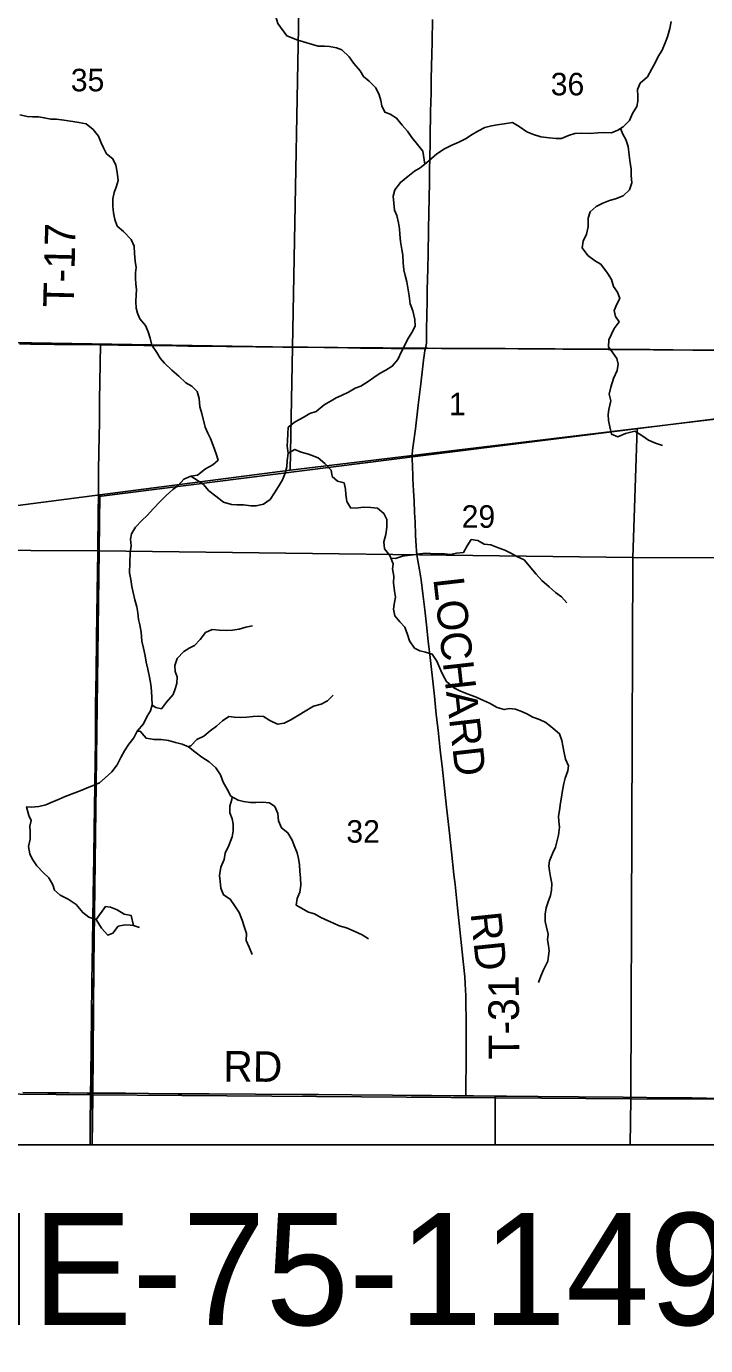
# Model space of a CAD drawing. Extents: x 0 to 1391, y -24 to 440.
# Drawn here: x 561.39 to 586.61, y 365.71 to 414.73 of the extents above; entities that cross this region are included whole.
import ezdxf

# ---------------------------------------------------------------- set-up
doc = ezdxf.new("R2010")
doc.units = 0
for name, color, linetype in [('GM_X_County_Road', 7, 'Continuous'), ('GM_X_County_Road_Text', 7, 'Continuous'), ('GM_X_Minor_Lake', 7, 'Continuous'), ('GM_X_Minor_River', 7, 'Continuous'), ('GM_X_Section', 7, 'Continuous'), ('GM_X_Section_Text', 7, 'Continuous'), ('GM_X_Township', 7, 'Continuous'), ('GM_X_Township_Road', 7, 'Continuous'), ('GM_X_Township_Road_Text', 7, 'Continuous'), ('SH_Text', 7, 'Continuous')]:
    doc.layers.add(name, color=color, linetype=linetype)

msp = doc.modelspace()

# ---------------------------------------------------------------- linework, layer by layer
at = {"layer": 'GM_X_County_Road'}
for points in [[(564.059, 397.238), (564.062, 397.431), (564.068, 398.202), (564.075, 398.935), (564.087, 399.469), (564.096, 400.053), (564.106, 400.997), (564.113, 401.358), (564.127, 402.339), (564.134, 402.762), (564.135, 402.895)], [(563.769, 375.097), (563.778, 375.648), (563.793, 376.916), (563.801, 377.91), (563.818, 379.215), (563.845, 380.668), (563.868, 382.408), (563.892, 383.874), (563.897, 384.905), (563.912, 385.712), (563.925, 386.508), (563.936, 387.464), (563.947, 388.148), (563.958, 389.515), (563.973, 390.695), (563.992, 391.975), (564.012, 393.715), (564.034, 395.207), (564.051, 396.735), (564.059, 397.238)], [(561.256, 375.121), (562.187, 375.111), (562.97, 375.104), (563.641, 375.098), (563.769, 375.097)], [(563.758, 373.178), (563.758, 373.598), (563.758, 374.045), (563.766, 374.89), (563.769, 375.097)], [(563.769, 375.097), (565.065, 375.091), (565.922, 375.085), (567.028, 375.073), (568.171, 375.067), (569.899, 375.056), (571.638, 375.043), (572.235, 375.04), (573.478, 375.033), (574.981, 375.015), (575.677, 375.009), (576.435, 375), (577.243, 374.994), (577.711, 374.991)], [(577.711, 374.991), (577.988, 374.99), (578.802, 374.985)], [(578.802, 374.985), (579.218, 374.982), (580.399, 374.97), (581.89, 374.958), (583.555, 374.941), (585.295, 374.925), (586.102, 374.916), (586.649, 374.909), (588.364, 374.891), (588.829, 374.885)]]:
    msp.add_lwpolyline(points, dxfattribs=at)
at = {"layer": 'GM_X_Minor_Lake'}
for points in [[(565.369, 381.317), (565.278, 381.693), (565.013, 381.737), (564.757, 381.901), (564.508, 381.997), (564.318, 382.024), (563.972, 381.544)], [(563.972, 381.544), (564.175, 381.224), (564.406, 380.962), (564.597, 381.041), (564.799, 381.302), (565.059, 381.349), (565.249, 381.338), (565.369, 381.317)]]:
    msp.add_lwpolyline(points, dxfattribs=at)
at = {"layer": 'GM_X_Minor_River'}
for points in [[(570.75, 418), (570.656, 415.079), (570.729, 414.828), (571.057, 414.376), (571.464, 414.211), (572.228, 413.996)], [(571.912, 400.349), (572.142, 400.413), (572.445, 400.665), (572.7, 400.812), (572.893, 400.922), (573.086, 401.016), (573.348, 401.14), (573.595, 401.287), (573.811, 401.366), (574.074, 401.535), (574.29, 401.683), (574.523, 401.845), (574.731, 401.955), (574.971, 402.102), (575.182, 402.348), (575.318, 402.65), (575.43, 402.86), (575.542, 403.094), (575.7, 403.349), (575.827, 403.59), (575.81, 403.841), (575.741, 404.162), (575.639, 404.415), (575.608, 404.72), (575.567, 404.942), (575.513, 405.24), (575.449, 405.477), (575.408, 405.676), (575.376, 405.943), (575.367, 406.232), (575.333, 406.438), (575.286, 406.736), (575.254, 407.01), (575.243, 407.201), (575.203, 407.43), (575.14, 407.705), (575.06, 407.897), (575.028, 408.164), (575.003, 408.416), (575.069, 408.65), (575.274, 408.927), (575.553, 409.149), (575.801, 409.342), (576.01, 409.467), (576.243, 409.659), (576.437, 409.822), (576.632, 409.986), (576.918, 410.177), (577.188, 410.316), (577.45, 410.425), (577.689, 410.549), (577.936, 410.711), (578.153, 410.835), (578.415, 410.967), (578.66, 411.038), (578.867, 411.071), (579.135, 411.103), (579.441, 411.15), (579.682, 411.008), (579.967, 410.812), (580.224, 410.715), (580.489, 410.625), (580.801, 410.581), (581.06, 410.56), (581.258, 410.563), (581.52, 410.679), (581.758, 410.75), (582.01, 410.76), (582.33, 410.753), (582.613, 410.77), (582.872, 410.78), (583.123, 410.767), (583.347, 410.868), (583.548, 411.001), (583.782, 411.232), (583.902, 411.488), (584.053, 411.751), (584.095, 411.948), (584.092, 412.138), (584.082, 412.382), (584.178, 412.615), (584.451, 412.853), (584.617, 413.146), (584.745, 413.402), (584.856, 413.605), (584.999, 413.845), (585.104, 414.117), (585.193, 414.343), (585.283, 414.646), (585.335, 414.911)], [(572.228, 413.996), (572.457, 413.993), (572.647, 413.974), (572.905, 413.931), (573.102, 413.85), (573.371, 413.601), (573.549, 413.354), (573.779, 413.075), (573.904, 412.859), (574.114, 412.695), (574.367, 412.446), (574.491, 412.185), (574.555, 411.97), (574.582, 411.78), (574.698, 411.534), (574.902, 411.461), (575.136, 411.319), (575.336, 411.063), (575.544, 410.831), (575.707, 410.599), (575.915, 410.336), (576.115, 410.096), (576.19, 409.614)], [(567.495, 398.01), (567.746, 398.053), (568.037, 398.284), (568.312, 398.44), (568.512, 398.611), (568.432, 398.848), (568.322, 399.16), (568.219, 399.42), (568.123, 399.611), (568.02, 399.832), (567.905, 400.35), (567.832, 400.593), (567.798, 400.905), (567.726, 401.156), (567.531, 401.364), (567.305, 401.488), (567.05, 401.735), (566.788, 401.951), (566.518, 402.212), (566.353, 402.404), (566.227, 402.611), (566.041, 402.886), (565.984, 403.145), (565.911, 403.374), (565.808, 403.611), (565.599, 403.864), (565.518, 404.07), (565.467, 404.26), (565.455, 404.511), (565.466, 404.753), (565.469, 404.943), (565.456, 405.163), (565.444, 405.361), (565.439, 405.573), (565.457, 405.77), (565.422, 406.006), (565.403, 406.287), (565.384, 406.56), (565.281, 406.812), (564.989, 407.105), (564.756, 407.305), (564.668, 407.549), (564.626, 407.8), (564.599, 408.051), (564.595, 408.316), (564.643, 408.558), (564.714, 408.755), (564.793, 409.004), (564.76, 409.316), (564.71, 409.574), (564.599, 409.811), (564.366, 409.996), (564.255, 410.21), (564.159, 410.401), (564.064, 410.653), (563.87, 410.891), (563.607, 411.107), (563.334, 411.156), (563.115, 411.189), (562.781, 411.239), (562.501, 411.281), (562.296, 411.284), (562.047, 411.333), (561.834, 411.366), (561.607, 411.362), (561.417, 411.379), (561.137, 411.436)], [(583.452, 410.938), (583.534, 410.727), (583.652, 410.519), (583.738, 410.259), (583.776, 409.939), (583.802, 409.74), (583.849, 409.42), (583.851, 409.191), (583.876, 408.917), (583.786, 408.66), (583.552, 408.429), (583.268, 408.314), (583.045, 408.258), (582.799, 408.164), (582.545, 408.033), (582.327, 407.832), (582.245, 407.598), (582.246, 407.278), (582.194, 407.013), (582.066, 406.742), (582.03, 406.499), (582.238, 406.213), (582.523, 406.009), (582.726, 405.891), (582.963, 405.559), (583.118, 405.327), (583.188, 405.059), (583.336, 404.858), (583.422, 404.613), (583.319, 404.41), (583.214, 404.169), (583.27, 403.947), (583.404, 403.754), (583.215, 403.507), (583.111, 403.296), (583.023, 403.077), (583.002, 402.827), (583.172, 402.595), (583.32, 402.386), (583.369, 402.172), (583.325, 401.937), (583.189, 401.644), (583.098, 401.326), (583.031, 401.061), (583.095, 400.809), (583.019, 400.491), (582.999, 400.301), (583.01, 400.088), (583.05, 399.844), (583.121, 399.576), (583.355, 399.479), (583.632, 399.603), (583.985, 399.687), (584.241, 399.521), (584.496, 399.348), (584.753, 399.244), (585.01, 399.155)], [(571.103, 398.865), (571.069, 399.131), (571.086, 399.328), (571.09, 399.593), (571.108, 399.836), (571.369, 400.037), (571.659, 400.193), (571.912, 400.349)], [(565.212, 394.42), (565.234, 395.173), (565.283, 395.422), (565.256, 395.673), (565.289, 395.878), (565.436, 396.126), (565.675, 396.373), (565.882, 396.568), (566.098, 396.8), (566.359, 397.07), (566.575, 397.294), (566.828, 397.526), (567.02, 397.668), (567.235, 397.908), (567.495, 398.01), (567.766, 397.84), (567.961, 397.701), (568.163, 397.47), (568.418, 397.27), (568.704, 397.053), (569.006, 396.958), (569.196, 396.948), (569.454, 396.952), (569.727, 396.918), (569.924, 396.915), (570.19, 396.972), (570.436, 397.151), (570.606, 397.392), (570.753, 397.633), (570.893, 397.881), (571.002, 398.13), (571.059, 398.357), (571.069, 398.6), (571.103, 398.865), (571.356, 399.013), (571.597, 398.911), (571.862, 398.839)], [(571.862, 398.839), (572.219, 398.7), (572.466, 398.481), (572.704, 398.24), (572.745, 398.004), (572.939, 397.832), (573.182, 397.774), (573.238, 397.529), (573.249, 397.338), (573.289, 397.079), (573.436, 396.832), (573.711, 396.842), (573.909, 396.86), (574.176, 396.854), (574.427, 396.826), (574.667, 396.631), (574.776, 396.4), (574.77, 396.119), (574.734, 395.853), (574.659, 395.581), (574.684, 395.322), (574.884, 395.074), (575.002, 394.764)], [(574.926, 394.965), (575.095, 394.963), (575.349, 395.049), (575.54, 395.068), (575.747, 395.094), (575.999, 395.126), (576.205, 395.152), (576.396, 395.141), (576.647, 395.128), (576.914, 395.13), (577.142, 395.109), (577.357, 395.15), (577.625, 395.183), (577.76, 395.431), (577.91, 395.663), (578.153, 395.628), (578.386, 395.493), (578.63, 395.465), (578.887, 395.361), (579.152, 395.272), (579.408, 395.144), (579.604, 395.034), (579.87, 394.905)], [(575.002, 394.764), (574.982, 394.569), (575.029, 394.302), (575.015, 394.058), (575.06, 393.738), (575.1, 393.523), (575.04, 393.259), (575.02, 393.069), (575.074, 392.824), (575.251, 392.599), (575.444, 392.411), (575.544, 392.135), (575.614, 391.897), (575.804, 391.626), (576, 391.522), (576.204, 391.479), (576.461, 391.404), (576.629, 391.148), (576.78, 390.802), (576.866, 390.61), (576.99, 390.386), (577.265, 390.151), (577.483, 390.039), (577.694, 389.957), (577.89, 389.884), (578.094, 389.81), (578.357, 389.682), (578.582, 389.585), (578.867, 389.418), (579.132, 389.343), (579.323, 389.383), (579.551, 389.362), (579.807, 389.257), (580.002, 389.168), (580.197, 389.057), (580.439, 388.975), (580.679, 388.87), (580.94, 388.65), (581.186, 388.446), (581.271, 388.2), (581.311, 388.001), (581.358, 387.734), (581.413, 387.496), (581.521, 387.258), (581.5, 387.068), (581.402, 386.797), (581.344, 386.6), (581.299, 386.343), (581.262, 386.092), (581.226, 385.88), (581.189, 385.592), (581.153, 385.38), (581.155, 385.189), (581.188, 384.975), (581.15, 384.68), (581.09, 384.43), (581.032, 384.234), (580.935, 384.023), (580.813, 383.729), (580.786, 383.54), (580.819, 383.348), (580.851, 383.127), (580.898, 382.882), (580.884, 382.639), (580.849, 382.442), (580.759, 382.201), (580.692, 381.982), (580.648, 381.739), (580.649, 381.465), (580.697, 381.259), (580.759, 381.006), (580.745, 380.786), (580.778, 380.579), (580.796, 380.381), (580.776, 380.191), (580.748, 380.002), (580.595, 379.671), (580.497, 379.437), (580.408, 379.204)], [(579.87, 394.905), (580.319, 394.381), (580.533, 394.14), (580.801, 393.905), (581.039, 393.693), (581.256, 393.528), (581.456, 393.31)], [(561.372, 385.732), (561.57, 385.721), (561.844, 385.739), (562.103, 385.811), (562.31, 385.89), (562.608, 386.014), (562.83, 386.109), (563.189, 386.255), (563.441, 386.349), (563.701, 386.459), (563.908, 386.531), (564.107, 386.626), (564.314, 386.812), (564.561, 387.036), (564.762, 387.297), (564.895, 387.568), (565.035, 387.808), (565.19, 388.063), (565.376, 388.295), (565.501, 388.536), (565.733, 388.82), (565.873, 389.098), (565.997, 389.3), (566.061, 389.519), (566.042, 389.777), (566.037, 390.035), (566.002, 390.278), (565.953, 390.544), (565.896, 390.84), (565.831, 391.106), (565.796, 391.342), (565.738, 391.623), (565.673, 391.882), (565.647, 392.223), (565.605, 392.497), (565.555, 392.694), (565.52, 392.937), (565.492, 393.165), (565.419, 393.416), (565.355, 393.698), (565.297, 393.919), (565.269, 394.177), (565.212, 394.42)], [(566.056, 389.502), (566.197, 389.426), (566.402, 389.377), (566.595, 389.624), (566.834, 389.908), (566.913, 390.119), (566.969, 390.315), (566.987, 390.557), (566.906, 390.755), (566.902, 390.983), (566.981, 391.247), (567.235, 391.5), (567.435, 391.626), (567.626, 391.721), (567.835, 391.952), (568.043, 392.207), (568.281, 392.324), (568.546, 392.289), (568.805, 392.285), (569.041, 392.296), (569.285, 392.33), (569.537, 392.402), (569.781, 392.451)], [(571.211, 388.965), (572.051, 389.476), (572.334, 389.545), (572.574, 389.668), (572.784, 389.883)], [(567.392, 387.963), (567.487, 388.003), (567.71, 388.227), (567.978, 388.351), (568.209, 388.559), (568.447, 388.722), (568.67, 388.931), (568.9, 389.086), (569.098, 389.068), (569.349, 389.048), (569.577, 389.06), (569.806, 389.086), (569.996, 389.098), (570.186, 389.088), (570.428, 388.94), (570.707, 388.806), (570.959, 388.84), (571.211, 388.965)], [(565.504, 388.539), (565.607, 388.541), (565.832, 388.28), (566.128, 388.23), (566.394, 388.233), (566.66, 388.198), (566.925, 388.118), (567.176, 388.061), (567.403, 387.959), (567.644, 387.773), (567.907, 387.572), (568.179, 387.408), (568.419, 387.184), (568.598, 386.916), (568.694, 386.642), (568.843, 386.382), (568.984, 386.13), (569.256, 385.981), (569.445, 385.933), (569.711, 385.89), (569.901, 385.895), (570.152, 385.906), (570.418, 385.879), (570.614, 385.739), (570.725, 385.48), (570.752, 385.207), (570.855, 384.947), (571.096, 384.761), (571.252, 384.494), (571.326, 384.296), (571.444, 384.021), (571.487, 383.816), (571.529, 383.572), (571.542, 383.337), (571.569, 383.079), (571.581, 382.821), (571.547, 382.564), (571.437, 382.324), (571.405, 382.076)], [(569.034, 386.102), (569.02, 386), (568.941, 385.759), (568.938, 385.509), (569.034, 385.28), (569.069, 385.09), (569.066, 384.833), (569.033, 384.613), (568.907, 384.297), (568.766, 384.012), (568.725, 383.777), (568.607, 383.484), (568.558, 383.182), (568.578, 382.969), (568.605, 382.711), (568.708, 382.459), (568.957, 382.304), (569.121, 382.059), (569.285, 381.806), (569.403, 381.524), (569.469, 381.28), (569.564, 381.021), (569.546, 380.764), (569.657, 380.512), (569.775, 380.245)], [(561.386, 385.731), (561.482, 385.412), (561.563, 385.221), (561.515, 385.009), (561.527, 384.805), (561.531, 384.532), (561.467, 384.26), (561.517, 383.987), (561.598, 383.796), (561.77, 383.543), (562.025, 383.281), (562.22, 383.096), (562.369, 382.828), (562.435, 382.638), (562.638, 382.445), (562.932, 382.296), (563.234, 382.102), (563.481, 381.802), (563.707, 381.632), (563.972, 381.544)], [(571.405, 382.076), (571.869, 381.817), (572.088, 381.758), (572.321, 381.622), (572.591, 381.494), (572.787, 381.405), (572.998, 381.309), (573.27, 381.233), (573.556, 381.112), (573.856, 380.975), (574.089, 380.832)], [(565.369, 381.317), (565.581, 381.245)]]:
    msp.add_lwpolyline(points, dxfattribs=at)
at = {"layer": 'GM_X_Section'}
for points in [[(551.455, 418), (551.127, 403.143), (571.263, 402.812), (571.559, 418)], [(571.559, 418), (571.263, 402.812), (591.378, 402.657), (591.649, 418)], [(563.85, 363.742), (563.869, 355.108), (543.666, 355.101), (543.747, 375.22), (563.826, 375.025), (563.83, 373.178)], [(563.83, 373.178), (563.826, 375.025), (583.829, 374.884), (583.805, 373.178)], [(583.805, 373.178), (583.829, 374.884), (603.924, 374.808), (604.127, 354.67), (583.55, 354.883), (583.674, 363.742)]]:
    msp.add_lwpolyline(points, dxfattribs=at)
for points in [[(551.127, 403.143), (571.263, 402.812), (571.178, 398.238), (564.116, 397.324), (550.964, 395.616)], [(571.263, 402.812), (591.378, 402.657), (591.313, 400.659), (584.064, 399.784), (571.178, 398.238)], [(591.313, 400.659), (604.081, 402.218), (604.024, 394.97), (583.906, 394.992), (584.064, 399.784)], [(571.178, 398.238), (584.064, 399.784), (583.906, 394.992), (564.092, 395.242), (564.116, 397.324)], [(550.964, 395.616), (564.116, 397.324), (564.092, 395.242), (548.844, 395.312)], [(564.092, 395.242), (563.826, 375.025), (543.747, 375.22), (543.962, 394.707), (548.844, 395.312)], [(583.906, 394.992), (583.829, 374.884), (563.826, 375.025), (564.092, 395.242)], [(604.024, 394.97), (603.924, 374.808), (583.829, 374.884), (583.906, 394.992)]]:
    msp.add_lwpolyline(points, close=True, dxfattribs=at)
at = {"layer": 'GM_X_Township'}
for points in [[(563.833, 373.178), (563.849, 374.981), (563.918, 383.057), (564.071, 397.264), (576.025, 398.776), (588.961, 400.394), (591.398, 400.66), (591.42, 402.56), (591.526, 412.457), (591.623, 418), (492, 418), (492, 315.227)], [(628, 342.724), (628, 405.073), (624.099, 404.552), (614.669, 403.388), (611.937, 403.101), (606.11, 402.437), (604.084, 402.185), (591.398, 400.66), (588.961, 400.394), (576.025, 398.776), (564.071, 397.264), (563.918, 383.057), (563.849, 374.981), (563.833, 373.178)]]:
    msp.add_lwpolyline(points, dxfattribs=at)
at = {"layer": 'GM_X_Township_Road'}
for points in [[(576.205, 402.763), (576.225, 402.835), (576.234, 402.89), (576.24, 402.953), (576.242, 403.158), (576.247, 403.419), (576.255, 404.065), (576.266, 404.45), (576.274, 404.935), (576.29, 405.717), (576.302, 406.289), (576.32, 407.134), (576.331, 407.855), (576.341, 408.277), (576.354, 409.01), (576.36, 409.358), (576.364, 409.892), (576.376, 410.377), (576.386, 410.936), (576.394, 411.222), (576.397, 411.571), (576.403, 411.893), (576.414, 412.269), (576.422, 412.75), (576.434, 413.259), (576.444, 413.669), (576.455, 414.166), (576.467, 414.986)], [(561.134, 402.928), (561.532, 402.924), (561.893, 402.922), (562.427, 402.914), (563.136, 402.91), (564.135, 402.895)], [(564.135, 402.895), (564.341, 402.892), (564.801, 402.885), (565.285, 402.885), (565.745, 402.875), (566.18, 402.876), (566.963, 402.859), (567.397, 402.851), (568.056, 402.845), (568.329, 402.841), (568.813, 402.834), (569.186, 402.834), (569.907, 402.825), (570.503, 402.816), (570.913, 402.808), (571.51, 402.805), (571.833, 402.804), (572.442, 402.797), (572.765, 402.792), (573.324, 402.781), (573.796, 402.774), (574.194, 402.769), (574.939, 402.759), (575.747, 402.752), (576.205, 402.763)], [(575.718, 398.768), (575.717, 398.814), (575.727, 398.976), (575.746, 399.161), (575.835, 399.776), (575.94, 400.652), (576.035, 401.442), (576.113, 402.108), (576.136, 402.331), (576.167, 402.589), (576.185, 402.681), (576.205, 402.763)], [(576.205, 402.763), (576.505, 402.767), (576.801, 402.764), (577.181, 402.764), (577.589, 402.764), (578.616, 402.761), (579.163, 402.76), (579.784, 402.753), (580.195, 402.749), (580.518, 402.746), (581.027, 402.741), (581.313, 402.74), (581.686, 402.738), (582.382, 402.734), (583.078, 402.729), (583.774, 402.724), (584.544, 402.719), (585.402, 402.706), (586.135, 402.702), (586.819, 402.697), (587.105, 402.697), (588.77, 402.692), (588.96, 402.69)], [(575.722, 398.488), (575.719, 398.566), (575.718, 398.768)], [(577.711, 374.991), (577.712, 375.127), (577.72, 376.444), (577.716, 377.798), (577.707, 378.457), (577.702, 378.705), (577.685, 379.152), (577.668, 379.412), (577.623, 379.87), (577.574, 380.339), (577.488, 381.155), (577.398, 381.982), (577.305, 382.847), (577.264, 383.218), (577.173, 384.058), (577.084, 384.86), (576.991, 385.713), (576.925, 386.306), (576.825, 387.245), (576.783, 387.628), (576.745, 387.961), (576.675, 388.578), (576.611, 389.159), (576.537, 389.838), (576.477, 390.394), (576.389, 391.172), (576.312, 391.889), (576.243, 392.494), (576.181, 393.05), (576.109, 393.642), (576.043, 394.16), (575.985, 394.54), (575.913, 394.944), (575.888, 395.103), (575.872, 395.239), (575.859, 395.413), (575.84, 395.822), (575.821, 396.319), (575.806, 396.667), (575.789, 397.101), (575.768, 397.473), (575.744, 397.92), (575.722, 398.488)], [(578.8, 373.178), (578.801, 373.25), (578.799, 374.232), (578.802, 374.866), (578.802, 374.985)]]:
    msp.add_lwpolyline(points, dxfattribs=at)
at = {"layer": 'SH_Text'}
msp.add_lwpolyline([(552.215, 373.178), (603.114, 373.178), (603.114, 363.742), (552.215, 363.742)], close=True, dxfattribs=at)

# ---------------------------------------------------------------- texts
at = {"layer": 'GM_X_County_Road_Text'}
msp.add_text('RD', height=1.1364, rotation=359.5056, dxfattribs=at).set_placement((568.693, 375.527))
at = {"layer": 'GM_X_Section_Text'}
for s, height, p in [('35', 0.8371, (563.035, 412.314)), ('36', 0.8371, (580.86, 412.164)), ('1', 0.837, (577.077, 400.281)), ('29', 0.8371, (577.552, 396.098)), ('32', 0.8371, (573.269, 384.398))]:
    msp.add_text(s, height=height, rotation=0, dxfattribs=at).set_placement(p)
at = {"layer": 'GM_X_Township_Road_Text'}
for s, rotation, p in [('T-17', 88.5753, (563.141, 404.272)), ('LOCHARD', 276.4632, (576.496, 394.203)), ('RD', 275.9066, (577.88, 381.776)), ('T-31', 90.3528, (579.691, 376.343))]:
    msp.add_text(s, height=1.1364, rotation=rotation, dxfattribs=at).set_placement(p)
at = {"layer": 'SH_Text'}
msp.add_text('SHE-75-1149 L/R', height=4.16667, dxfattribs=at).set_placement((553.861, 366.476))

doc.saveas('drawing.dxf')
